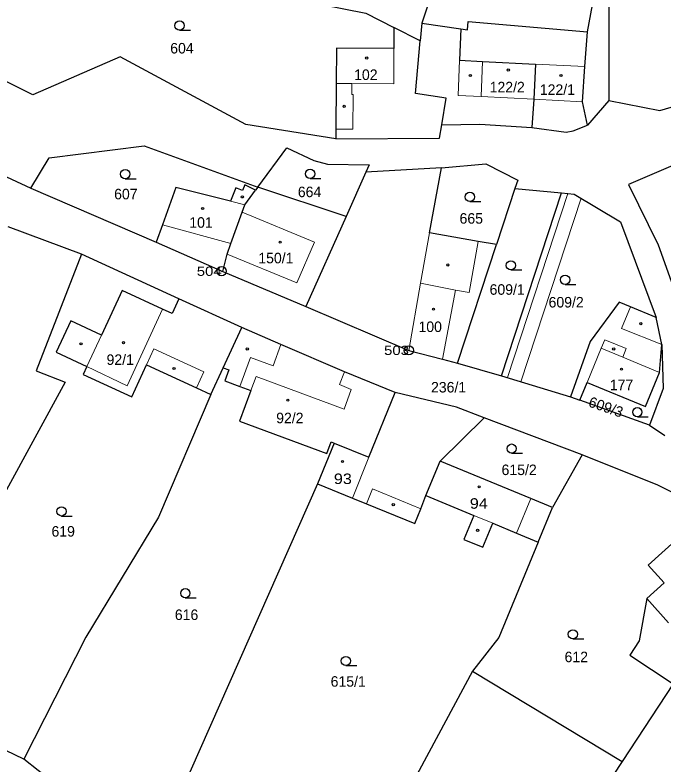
# Model space of a CAD drawing. Extents: x -754445 to -751443, y -1030748 to -1028224.
# Drawn here: x -752770.5 to -752665.6, y -1029243.8 to -1029122.6 of the extents above; entities that cross this region are included whole.
import ezdxf
from ezdxf.enums import TextEntityAlignment as Align

# ---------------------------------------------------------------- set-up
doc = ezdxf.new("R2010")
doc.units = 0
doc.header["$LTSCALE"] = 0.68
for name, color, linetype, lineweight in [('1', 7, 'Continuous', 25), ('13', 7, 'Continuous', 13), ('3', 7, 'Continuous', 25), ('4', 7, 'Continuous', 13), ('5', 7, 'Continuous', 25), ('8', 7, 'Continuous', 25)]:
    doc.layers.add(name, color=color, linetype=linetype, lineweight=lineweight)
doc.layers.add('2', color=7, linetype='Continuous')

msp = doc.modelspace()

# ---------------------------------------------------------------- linework, layer by layer
at = {"layer": '1'}
for p, q in [((-752704.67, -1029123.9), (-752704.93, -1029126.78)), ((-752704.67, -1029123.9), (-752698.32, -1029124.83)), ((-752674.39, -1029136.41), (-752677.81, -1029140.38)), ((-752767.93, -1029150.61), (-752747.67, -1029159.35)), ((-752731.18, -1029150.42), (-752731.57, -1029150.95)), ((-752716.91, -1029155.19), (-752731.18, -1029150.42)), ((-752689.57, -1029150.68), (-752692.56, -1029159.75)), ((-752691.76, -1029180.97), (-752682.05, -1029151.37)), ((-752759.72, -1029161.31), (-752771.6, -1029156.88)), ((-752747.67, -1029159.35), (-752736.86, -1029164.09)), ((-752743.96, -1029168.51), (-752759.72, -1029161.31)), ((-752736.86, -1029164.09), (-752723.42, -1029169.77)), ((-752733.78, -1029173.17), (-752743.96, -1029168.51)), ((-752698.89, -1029178.95), (-752691.76, -1029180.97)), ((-752691.76, -1029180.97), (-752680.59, -1029184.4)), ((-752680.59, -1029184.4), (-752679.05, -1029184.93)), ((-752667.77, -1029188.99), (-752679.05, -1029184.93)), ((-752678.71, -1029193.79), (-752694.54, -1029187.77)), ((-752718.85, -1029191.87), (-752721.54, -1029198.49)), ((-752678.71, -1029193.79), (-752683.48, -1029202.31)), ((-752685.79, -1029207.91), (-752683.48, -1029202.31)), ((-752696.43, -1029228.8), (-752672.22, -1029243.44)), ((-752663.96, -1029230.83), (-752672.22, -1029243.44)), ((-752751.66, -1029256.75), (-752769.05, -1029243.04))]:
    msp.add_line(p, q, dxfattribs=at)
for points in [[(-752668.67, -1029091.51), (-752674.37, -1029118.71), (-752674.39, -1029136.41)], [(-752760.57, -1029109.57), (-752753.18, -1029113.62), (-752740.82, -1029118.28), (-752724.1, -1029120.25), (-752713.71, -1029122.28), (-752709.15, -1029124.62)], [(-752675.58, -1029116.36), (-752680.85, -1029115.08), (-752679.65, -1029110.57), (-752686.61, -1029109.83), (-752687.21, -1029115.55), (-752702.58, -1029113.93), (-752703.16, -1029119.45), (-752704.67, -1029123.9)], [(-752677.84, -1029125.32), (-752676.99, -1029120.94), (-752675.58, -1029116.36)], [(-752718.55, -1029142.62), (-752733.14, -1029140.28), (-752753.5, -1029129.34), (-752767.6, -1029135.5), (-752780.85, -1029128.93), (-752781.24, -1029119.49)], [(-752698.32, -1029124.83), (-752697.24, -1029124.99), (-752697.12, -1029123.62), (-752677.84, -1029125.32)], [(-752709.15, -1029124.62), (-752709.17, -1029128), (-752718.47, -1029127.95), (-752718.5, -1029133.66), (-752718.54, -1029141.05), (-752718.55, -1029142.62)], [(-752701.4, -1029140.37), (-752700.68, -1029136.03), (-752705.68, -1029135.26), (-752704.93, -1029126.78), (-752709.15, -1029124.62)], [(-752698.32, -1029124.83), (-752698.52, -1029129.89), (-752694.81, -1029130.08), (-752686.23, -1029130.51), (-752686.52, -1029136.21), (-752686.83, -1029140.79)], [(-752677.81, -1029140.38), (-752678.61, -1029136.64), (-752678.23, -1029130.92), (-752677.84, -1029125.32)], [(-752674.39, -1029136.41), (-752666.09, -1029138.01), (-752628.44, -1029126.95)], [(-752794.58, -1029137.39), (-752782.92, -1029143.65), (-752767.93, -1029150.61)], [(-752718.55, -1029142.62), (-752701.76, -1029142.52), (-752701.4, -1029140.37)], [(-752701.4, -1029140.37), (-752695.27, -1029140.25), (-752686.83, -1029140.79)], [(-752686.83, -1029140.79), (-752681.28, -1029141.54), (-752680.14, -1029141.32), (-752677.81, -1029140.38)], [(-752767.93, -1029150.61), (-752764.98, -1029145.72), (-752749.61, -1029143.74), (-752731.18, -1029150.42)], [(-752731.18, -1029150.42), (-752726.5, -1029144.05), (-752722.13, -1029146.14), (-752719.9, -1029146.7), (-752713.17, -1029146.82), (-752713.72, -1029148.04)], [(-752660.94, -1029146.49), (-752661.38, -1029145.82), (-752671.19, -1029149.99), (-752666.38, -1029159.76), (-752662.64, -1029170.19)], [(-752701.46, -1029147.33), (-752694.29, -1029146.68), (-752689.12, -1029149.3), (-752689.57, -1029150.68), (-752682.05, -1029151.37)], [(-752701.46, -1029147.33), (-752713.72, -1029148.04), (-752716.91, -1029155.19), (-752723.42, -1029169.77)], [(-752692.56, -1029159.75), (-752695.52, -1029159.23), (-752703.38, -1029157.86), (-752701.46, -1029147.33)], [(-752731.57, -1029150.95), (-752733.32, -1029150.07), (-752733.67, -1029150.98), (-752734.78, -1029150.56), (-752735.6, -1029152.71), (-752744.48, -1029150.51), (-752746.65, -1029156.53), (-752747.67, -1029159.35)], [(-752736.86, -1029164.09), (-752736.17, -1029161.28), (-752735.54, -1029159.54), (-752733.73, -1029154.5), (-752733.29, -1029153.28), (-752731.57, -1029150.95)], [(-752682.05, -1029151.37), (-752679.99, -1029151.56), (-752672.47, -1029156.08), (-752666.71, -1029171.54)], [(-752723.42, -1029169.77), (-752706.74, -1029176.86), (-752701.31, -1029178.31), (-752698.89, -1029178.95), (-752692.56, -1029159.75)], [(-752759.72, -1029161.31), (-752767.1, -1029180.19), (-752762.38, -1029182.03), (-752777.16, -1029209.04)], [(-752743.96, -1029168.51), (-752745.05, -1029170.89), (-752746.61, -1029170.17), (-752753.15, -1029167.16), (-752756.51, -1029174.41), (-752761.46, -1029172.07), (-752763.83, -1029177.17), (-752758.87, -1029179.5), (-752759.46, -1029180.77), (-752751.61, -1029184.41), (-752749.22, -1029179.21), (-752741.13, -1029182.93), (-752738.78, -1029184.01)], [(-752666.71, -1029171.54), (-752670.87, -1029169.83), (-752672.72, -1029169.07), (-752677.38, -1029175.42), (-752680.59, -1029184.4)], [(-752679.05, -1029184.93), (-752677.88, -1029182.08), (-752668.43, -1029185.97), (-752666.15, -1029180.42), (-752665.8, -1029175.91), (-752666.71, -1029171.54)], [(-752738.78, -1029184.01), (-752736.78, -1029179.67), (-752733.78, -1029173.17)], [(-752708.94, -1029183.7), (-752717.16, -1029180.36), (-752727.45, -1029175.89), (-752733.78, -1029173.17)], [(-752665.8, -1029175.91), (-752665.56, -1029183.03), (-752667.77, -1029188.99), (-752665.3, -1029190.67)], [(-752736.78, -1029179.67), (-752735.87, -1029180), (-752736.53, -1029181.78), (-752734.1, -1029182.69), (-752732.31, -1029183.35), (-752734.16, -1029188.32), (-752720.01, -1029193.57), (-752719.31, -1029191.68), (-752718.85, -1029191.87)], [(-752738.78, -1029184.01), (-752747.28, -1029203.86), (-752759.05, -1029223.31), (-752769.05, -1029243.04)], [(-752718.85, -1029191.87), (-752713.2, -1029194.17), (-752708.94, -1029183.7)], [(-752694.54, -1029187.77), (-752699.02, -1029186.07), (-752708.94, -1029183.7)], [(-752721.54, -1029198.49), (-752715.89, -1029200.79), (-752713.62, -1029201.71), (-752705.79, -1029204.9), (-752704.81, -1029202.49), (-752703.99, -1029200.36), (-752701.69, -1029194.79), (-752694.54, -1029187.77)], [(-752657.82, -1029202.99), (-752666.44, -1029198.67), (-752678.71, -1029193.79)], [(-752683.48, -1029202.31), (-752686.99, -1029200.86), (-752701.69, -1029194.79)], [(-752721.54, -1029198.49), (-752748.46, -1029259.28), (-752751.66, -1029256.75)], [(-752703.99, -1029200.36), (-752696.22, -1029203.58), (-752697.83, -1029207.46), (-752694.75, -1029208.74), (-752693.15, -1029204.86), (-752689.31, -1029206.45), (-752685.79, -1029207.91)], [(-752652.37, -1029209.29), (-752656.21, -1029213.3), (-752659.72, -1029209.39), (-752660.44, -1029210.03), (-752663.02, -1029207.16), (-752667.98, -1029211.62), (-752665.4, -1029214.49), (-752668.24, -1029217.04), (-752669.45, -1029223.88), (-752670.98, -1029226.22), (-752663.96, -1029230.83)], [(-752685.79, -1029207.91), (-752692.16, -1029223.36), (-752696.43, -1029228.8), (-752722.35, -1029277.04)], [(-752769.05, -1029243.04), (-752784.83, -1029235.47), (-752785.73, -1029234.14)], [(-752672.22, -1029243.44), (-752673.66, -1029245.63), (-752668.9, -1029250.46)]]:
    msp.add_lwpolyline(points, dxfattribs=at)
at = {"layer": '13'}
msp.add_lwpolyline([(-752678.86, -1029152.24), (-752679.99, -1029151.56), (-752681.03, -1029151.47), (-752690.8, -1029181.27), (-752688.6, -1029181.94)], close=True, dxfattribs=at)
at = {"layer": '3'}
for p, q in [((-752743.863, -1029125.03), (-752742.113, -1029125.03)), ((-752752.663, -1029149.08), (-752750.913, -1029149.08)), ((-752722.733, -1029149.03), (-752720.983, -1029149.03)), ((-752696.863, -1029152.77), (-752695.113, -1029152.77)), ((-752690.223, -1029163.85), (-752688.473, -1029163.85)), ((-752681.453, -1029166.18), (-752679.703, -1029166.18)), ((-752669.753, -1029187.62), (-752668.003, -1029187.62)), ((-752690.103, -1029193.52), (-752688.353, -1029193.52)), ((-752762.973, -1029203.68), (-752761.223, -1029203.68)), ((-752742.933, -1029216.93), (-752741.183, -1029216.93)), ((-752680.193, -1029223.58), (-752678.443, -1029223.58)), ((-752716.933, -1029227.9), (-752715.183, -1029227.9))]:
    msp.add_line(p, q, dxfattribs=at)
for centre in [(-752743.8629, -1029124.2798), (-752752.6629, -1029148.3298), (-752722.7329, -1029148.2798), (-752696.8629, -1029152.0198), (-752690.2229, -1029163.0998), (-752681.4529, -1029165.4298), (-752669.7529, -1029186.8698), (-752690.1029, -1029192.7698), (-752762.9729, -1029202.9298), (-752742.9329, -1029216.1798), (-752680.1929, -1029222.8298), (-752716.9329, -1029227.1498)]:
    msp.add_circle(centre, 0.75, dxfattribs=at)
at = {"layer": '4'}
for p, q in [((-752709.2, -1029133.71), (-752709.17, -1029128)), ((-752698.52, -1029129.89), (-752698.75, -1029135.59)), ((-752694.81, -1029130.08), (-752695.04, -1029135.74)), ((-752678.23, -1029130.92), (-752686.23, -1029130.51)), ((-752716, -1029133.67), (-752718.5, -1029133.66)), ((-752709.2, -1029133.71), (-752716, -1029133.67)), ((-752716, -1029133.67), (-752716, -1029135.42)), ((-752716, -1029135.42), (-752715.76, -1029135.42)), ((-752715.76, -1029135.42), (-752715.79, -1029141.07)), ((-752695.04, -1029135.74), (-752698.75, -1029135.59)), ((-752686.52, -1029136.21), (-752695.04, -1029135.74)), ((-752678.61, -1029136.64), (-752686.52, -1029136.21)), ((-752718.54, -1029141.05), (-752715.79, -1029141.07)), ((-752733.29, -1029153.28), (-752735.6, -1029152.71)), ((-752722.04, -1029159.32), (-752733.73, -1029154.5)), ((-752735.54, -1029159.54), (-752746.65, -1029156.53)), ((-752704.86, -1029165.96), (-752703.38, -1029157.86)), ((-752724.88, -1029165.93), (-752722.04, -1029159.32)), ((-752696.96, -1029167.51), (-752695.52, -1029159.23)), ((-752736.17, -1029161.28), (-752724.88, -1029165.93)), ((-752706.74, -1029176.86), (-752704.86, -1029165.96)), ((-752704.86, -1029165.96), (-752699.18, -1029167.12)), ((-752701.31, -1029178.31), (-752699.18, -1029167.12)), ((-752699.18, -1029167.12), (-752696.96, -1029167.51)), ((-752672.31, -1029173.34), (-752670.87, -1029169.83)), ((-752752.32, -1029182.58), (-752746.61, -1029170.17)), ((-752665.8, -1029175.91), (-752672.31, -1029173.34)), ((-752758.87, -1029179.5), (-752756.51, -1029174.41)), ((-752728.73, -1029179.35), (-752727.45, -1029175.89)), ((-752675.03, -1029175.14), (-752675.6, -1029176.53)), ((-752675.03, -1029175.14), (-752671.56, -1029176.57)), ((-752749.22, -1029179.21), (-752748.03, -1029176.62)), ((-752739.94, -1029180.35), (-752748.03, -1029176.62)), ((-752675.6, -1029176.53), (-752677.88, -1029182.08)), ((-752734.1, -1029182.69), (-752732.36, -1029178)), ((-752732.36, -1029178), (-752728.73, -1029179.35)), ((-752672.13, -1029177.96), (-752666.15, -1029180.42)), ((-752758.87, -1029179.5), (-752752.32, -1029182.58)), ((-752741.13, -1029182.93), (-752739.94, -1029180.35)), ((-752717.99, -1029182.39), (-752717.16, -1029180.36)), ((-752732.31, -1029183.35), (-752731.48, -1029181.1)), ((-752731.48, -1029181.1), (-752717.22, -1029186.4)), ((-752716.06, -1029183.18), (-752717.99, -1029182.39)), ((-752716.06, -1029183.18), (-752717.22, -1029186.4)), ((-752715.89, -1029200.79), (-752713.2, -1029194.17)), ((-752712.64, -1029199.3), (-752713.62, -1029201.71)), ((-752704.81, -1029202.49), (-752712.64, -1029199.3)), ((-752689.31, -1029206.45), (-752686.99, -1029200.86)), ((-752696.22, -1029203.58), (-752693.15, -1029204.86)), ((-752664.73, -1029220.95), (-752668.24, -1029217.04))]:
    msp.add_line(p, q, dxfattribs=at)
msp.add_lwpolyline([(-752675.6, -1029176.53), (-752672.13, -1029177.96), (-752671.56, -1029176.57)], dxfattribs=at)
at = {"layer": '5'}
for centre in [(-752713.5668, -1029129.5392), (-752696.7868, -1029132.3692), (-752690.6468, -1029131.4792), (-752682.1268, -1029132.3592), (-752717.2068, -1029137.3692), (-752733.6968, -1029152.0192), (-752740.1268, -1029153.8992), (-752727.5668, -1029159.3392), (-752700.4268, -1029163.0392), (-752702.7468, -1029170.1992), (-752669.1968, -1029172.5292), (-752759.8068, -1029175.7992), (-752752.9368, -1029175.6192), (-752732.8968, -1029176.6292), (-752673.5868, -1029176.6292), (-752744.7568, -1029179.8092), (-752672.3268, -1029179.8992), (-752726.3268, -1029184.9292), (-752717.4968, -1029194.8492), (-752695.3668, -1029198.9592), (-752709.2668, -1029201.8292), (-752695.6068, -1029205.9892)]:
    msp.add_circle(centre, 0.175, dxfattribs=at)
at = {"layer": '8'}
for centre, radius in [((-752737.05, -1029164.0498), 0.75), ((-752737.05, -1029164.0498), 0.03), ((-752706.74, -1029176.8598), 0.75), ((-752706.74, -1029176.8598), 0.03)]:
    msp.add_circle(centre, radius, dxfattribs=at)

# ---------------------------------------------------------------- texts
at = {"layer": '2'}
for s, p in [('604', (-752743.479, -1029128.8)), ('102', (-752713.709, -1029133.09)), ('122/2', (-752690.82, -1029135.09)), ('122/1', (-752682.7, -1029135.5)), ('607', (-752752.559, -1029152.41)), ('664', (-752722.819, -1029152.06)), ('101', (-752740.389, -1029157.01)), ('665', (-752696.639, -1029156.35)), ('150/1', (-752728.27, -1029162.77)), ('609/1', (-752690.83, -1029167.86)), ('609/2', (-752681.28, -1029169.92)), ('100', (-752703.289, -1029173.89)), ('92/1', (-752753.47, -1029179.22)), ('236/1', (-752700.31, -1029183.68)), ('177', (-752672.319, -1029183.31)), ('92/2', (-752726.01, -1029188.66)), ('615/2', (-752688.89, -1029197.05)), ('619', (-752762.699, -1029207.01)), ('616', (-752742.729, -1029220.51)), ('612', (-752679.639, -1029227.34)), ('615/1', (-752716.56, -1029231.31))]:
    msp.add_text(s, height=1.7, dxfattribs=at).set_placement(p, align=Align.CENTER)
msp.add_text('609/3', height=1.7, rotation=341, dxfattribs=at).set_placement((-752675.1122, -1029186.8364), align=Align.CENTER)
at = {"layer": '2', "width": 1.15}
for s, p in [('93', (-752717.43, -1029198.5)), ('94', (-752695.42, -1029202.5))]:
    msp.add_text(s, height=1.7, dxfattribs=at).set_placement(p, align=Align.CENTER)
at = {"layer": '8', "width": 1.2}
for s, p in [('504', (-752737.05, -1029164.8)), ('503', (-752706.74, -1029177.61))]:
    msp.add_text(s, height=1.5, dxfattribs=at).set_placement(p, align=Align.RIGHT)

doc.saveas('drawing.dxf')
